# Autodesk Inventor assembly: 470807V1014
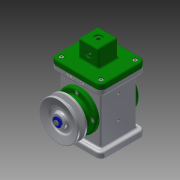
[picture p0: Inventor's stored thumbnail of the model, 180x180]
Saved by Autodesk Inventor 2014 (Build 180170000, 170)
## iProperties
Created: 2017-08
Part Number: 470807V1014
Document SubType Name: Assembly
Designer: 학생용
Author: 학생용
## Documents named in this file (18)
- C:\Users\net\Desktop\470807V1014\470807V1014.iam
- C:\Users\net\Desktop\470807V1014\470807V1014.ipt
- C:\Users\net\Desktop\470807V1014\E-링.ipt
- C:\Users\net\Desktop\470807V1014\V-벨트풀리.ipt
- C:\Users\net\Desktop\470807V1014\덮개.ipt
- C:\Users\net\Desktop\470807V1014\뒤커버.ipt
- C:\Users\net\Desktop\470807V1014\링크.ipt
- C:\Users\net\Desktop\470807V1014\베어링 17 x 40 x 12.ipt
- C:\Users\net\Desktop\470807V1014\볼트 M4 x 8.ipt
- C:\Users\net\Desktop\470807V1014\볼트 M4 x 10.ipt
- C:\Users\net\Desktop\470807V1014\슬라이더.ipt
- C:\Users\net\Desktop\470807V1014\앞커버.ipt
- C:\Users\net\Desktop\470807V1014\오일 실 17 30 8.ipt
- C:\Users\net\Desktop\470807V1014\와셔 4x16.ipt
- C:\Users\net\Desktop\470807V1014\클레비스 핀 6 x 22.ipt
- 클레비스 핀 6 x 22.ipt
- C:\Users\net\Desktop\470807V1014\키 4 x 4 x 12.ipt
- C:\Users\net\Desktop\470807V1014\편심축.ipt
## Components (3 placed, 3 different names)
1. 470807V1014:1
2. E-링:1
3. V-벨트풀리:1
